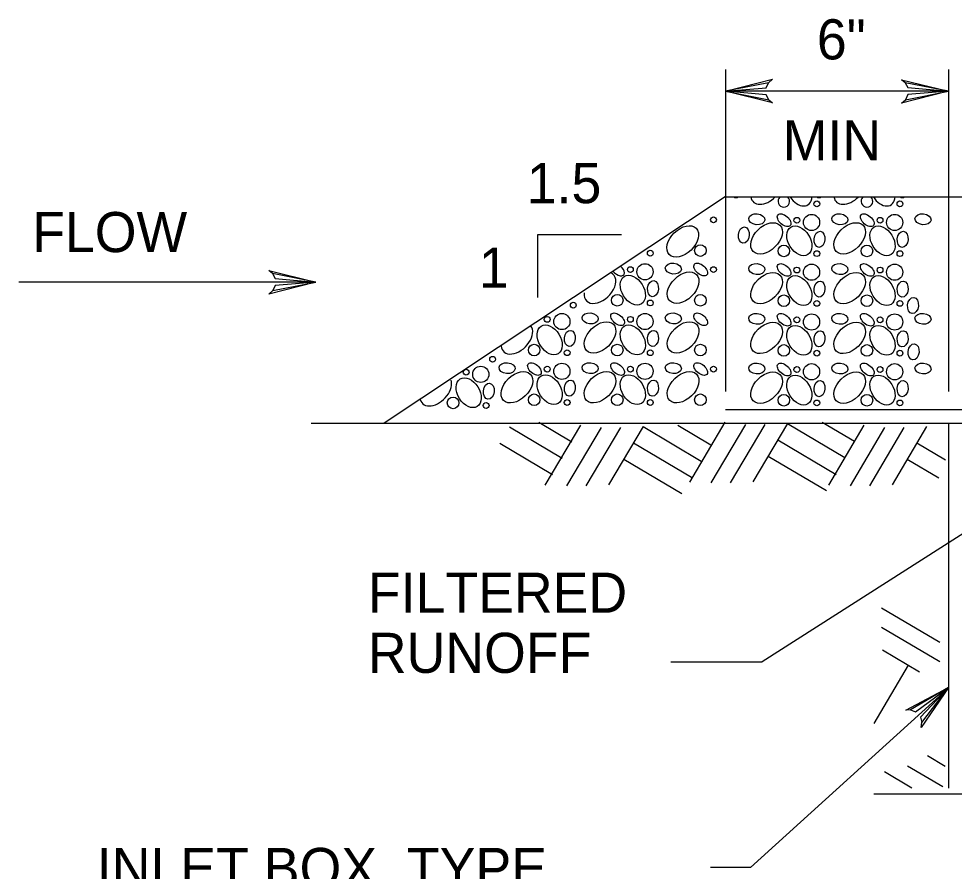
# Model space of a CAD drawing. Extents: x 636183 to 639890, y 299162 to 300538.
# Drawn here: x 637367.4 to 637437.3, y 299792.8 to 299856.5 of the extents above; entities that cross this region are included whole.
import ezdxf

# ---------------------------------------------------------------- set-up
doc = ezdxf.new("R2010")
doc.units = 0
doc.layers.add('Default', color=7, linetype='Continuous')

msp = doc.modelspace()

# ---------------------------------------------------------------- linework, layer by layer
at = {"layer": 'Default'}
for p, q in [((637436.88, 299852.669), (637436.88, 299828.614)), ((637420.211, 299843.151), (637394.729, 299826.243)), ((637420.211, 299843.151), (637445.22, 299843.151)), ((637406.216, 299835.651), (637406.216, 299840.337)), ((637406.216, 299840.337), (637412.465, 299840.337)), ((637420.235, 299827.262), (637489.98, 299827.262)), ((637406.277, 299826.319), (637408.745, 299824.856)), ((637420.181, 299826.319), (637417.528, 299821.842)), ((637427.459, 299826.319), (637429.864, 299824.894)), ((637389.258, 299826.243), (637420.235, 299826.243)), ((637404.076, 299825.979), (637408.025, 299823.639)), ((637409.394, 299826.096), (637406.741, 299821.62)), ((637410.929, 299825.914), (637408.352, 299821.565)), ((637412.379, 299825.914), (637409.802, 299821.565)), ((637414.07, 299825.994), (637411.493, 299821.645)), ((637414.07, 299825.994), (637418.42, 299823.417)), ((637416.672, 299826.096), (637419.14, 299824.633)), ((637421.717, 299826.136), (637419.139, 299821.787)), ((637420.235, 299826.243), (637489.98, 299826.243)), ((637423.166, 299826.136), (637420.589, 299821.787)), ((637424.858, 299826.217), (637422.28, 299821.868)), ((637424.858, 299826.217), (637429.143, 299823.678)), ((637430.576, 299826.096), (637427.923, 299821.62)), ((637432.111, 299825.914), (637429.534, 299821.565)), ((637433.561, 299825.914), (637430.984, 299821.565)), ((637435.252, 299825.994), (637432.675, 299821.645)), ((637436.88, 299826.243), (637436.88, 299798.98)), ((637424.137, 299825.001), (637428.486, 299822.423)), ((637403.355, 299824.763), (637407.304, 299822.423)), ((637413.349, 299824.778), (637417.699, 299822.201)), ((637448.335, 299824.623), (637422.968, 299808.402)), ((637434.532, 299824.778), (637436.675, 299823.508)), ((637412.629, 299823.562), (637416.978, 299820.985)), ((637423.416, 299823.785), (637427.765, 299821.207)), ((637433.811, 299823.562), (637436.178, 299822.159)), ((637436.234, 299809.849), (637431.885, 299812.426)), ((637436.234, 299808.399), (637431.885, 299810.977)), ((637434.73, 299807.647), (637431.966, 299809.285)), ((637416.154, 299808.402), (637422.968, 299808.402)), ((637433.882, 299808.15), (637431.305, 299803.8)), ((637436.766, 299806.354), (637422.107, 299793.047)), ((637436.639, 299800.597), (637435.318, 299801.38)), ((637436.457, 299799.062), (637433.823, 299800.622)), ((637434.149, 299798.98), (637432.108, 299800.19)), ((637431.312, 299798.538), (637455.154, 299798.538)), ((637422.107, 299793.047), (637419.109, 299793.047))]:
    msp.add_line(p, q, dxfattribs=at)
for points in [[(637420.235, 299852.669), (637420.235, 299828.614)], [(637423.467, 299850.419), (637423.736, 299850.196), (637420.235, 299851.057), (637423.467, 299850.419), (637423.271, 299850.792), (637420.235, 299851.057), (637423.264, 299851.316), (637423.447, 299851.691), (637420.235, 299851.057), (637423.729, 299851.945), (637423.447, 299851.691)], [(637433.648, 299851.694), (637433.379, 299851.918), (637436.88, 299851.057), (637433.648, 299851.694), (637433.845, 299851.321), (637436.88, 299851.057), (637433.851, 299850.798), (637433.669, 299850.422), (637436.88, 299851.057), (637433.386, 299850.169), (637433.669, 299850.422)], [(637436.88, 299851.057), (637420.235, 299851.057)], [(637386.377, 299837.422), (637386.107, 299837.645), (637389.609, 299836.784), (637386.377, 299837.422), (637386.573, 299837.049), (637389.609, 299836.784), (637386.579, 299836.525), (637386.397, 299836.15), (637389.609, 299836.784), (637386.114, 299835.896), (637386.397, 299836.15)], [(637389.609, 299836.784), (637367.415, 299836.784)], [(637434.042, 299804.815), (637433.693, 299804.803), (637436.881, 299806.487), (637434.042, 299804.815), (637434.437, 299804.667), (637436.881, 299806.487), (637434.79, 299804.28), (637434.903, 299803.878), (637436.881, 299806.487), (637434.86, 299803.501), (637434.903, 299803.878)]]:
    msp.add_lwpolyline(points, dxfattribs=at)
for centre, radius in [((637427.055, 299842.636), 0.217), ((637433.266, 299842.636), 0.217), ((637419.33, 299841.443), 0.217), ((637426.659, 299841.247), 0.606), ((637432.869, 299841.247), 0.606), ((637425.564, 299841.411), 0.217), ((637431.775, 299841.411), 0.217), ((637418.353, 299839.15), 0.435), ((637424.587, 299839.117), 0.435), ((637430.798, 299839.117), 0.435), ((637414.611, 299838.949), 0.217), ((637427.055, 299838.917), 0.217), ((637433.266, 299838.917), 0.217), ((637414.214, 299837.561), 0.606), ((637413.119, 299837.724), 0.217), ((637419.33, 299837.724), 0.217), ((637425.564, 299837.692), 0.217), ((637426.659, 299837.529), 0.606), ((637431.775, 299837.692), 0.217), ((637432.869, 299837.529), 0.606), ((637412.142, 299835.431), 0.435), ((637414.611, 299835.23), 0.217), ((637418.353, 299835.431), 0.435), ((637424.587, 299835.398), 0.435), ((637427.055, 299835.198), 0.217), ((637430.798, 299835.398), 0.435), ((637433.266, 299835.198), 0.217), ((637408.855, 299835.068), 0.217), ((637406.908, 299834.005), 0.217), ((637408.003, 299833.842), 0.606), ((637413.119, 299834.005), 0.217), ((637414.214, 299833.842), 0.606), ((637425.564, 299833.973), 0.217), ((637426.659, 299833.81), 0.606), ((637431.775, 299833.973), 0.217), ((637432.869, 299833.81), 0.606), ((637405.931, 299831.712), 0.435), ((637412.142, 299831.712), 0.435), ((637418.353, 299831.712), 0.435), ((637424.587, 299831.679), 0.435), ((637430.798, 299831.679), 0.435), ((637402.828, 299831.023), 0.217), ((637408.4, 299831.512), 0.217), ((637414.611, 299831.512), 0.217), ((637427.055, 299831.479), 0.217), ((637433.266, 299831.479), 0.217), ((637401.943, 299829.896), 0.606), ((637406.908, 299830.287), 0.217), ((637408.003, 299830.124), 0.606), ((637413.119, 299830.287), 0.217), ((637414.214, 299830.124), 0.606), ((637419.33, 299830.287), 0.217), ((637425.564, 299830.254), 0.217), ((637426.659, 299830.091), 0.606), ((637431.775, 299830.254), 0.217), ((637432.869, 299830.091), 0.606), ((637400.849, 299830.059), 0.217), ((637405.931, 299827.993), 0.435), ((637412.142, 299827.993), 0.435), ((637418.353, 299827.993), 0.435), ((637424.587, 299827.961), 0.435), ((637430.798, 299827.961), 0.435), ((637399.872, 299827.765), 0.435), ((637402.34, 299827.565), 0.217), ((637408.4, 299827.793), 0.217), ((637414.611, 299827.793), 0.217), ((637427.055, 299827.76), 0.217), ((637433.266, 299827.76), 0.217)]:
    msp.add_circle(centre, radius, dxfattribs=at)
for centre in [(637424.587, 299842.836), (637430.798, 299842.836)]:
    msp.add_arc(centre, 0.435, 133.46882, 46.53118, dxfattribs=at)
for centre, major_axis, ratio, start_param, end_param in [((637421.045, 299843.705), (0.061, 0.603), 0.672414, 2.796883, 3.62207), ((637423.296, 299843.776), (1.003, 0.982), 0.641702, 2.711952, 4.731495), ((637425.749, 299843.594), (-0.638, 1.03), 0.672414, 1.584156, 3.909428), ((637427.256, 299843.705), (0.061, 0.603), 0.672414, 2.796883, 3.62207), ((637429.507, 299843.776), (1.003, 0.982), 0.641702, 2.711952, 4.731495), ((637431.96, 299843.594), (-0.638, 1.03), 0.672414, 1.584156, 3.909428), ((637433.467, 299843.705), (0.061, 0.603), 0.672414, 2.796883, 3.62207), ((637410.851, 299836.371), (1.003, 0.982), 0.641702, 2.49155, 6.51241), ((637412.167, 299837.728), (0.459, -0.397), 0.56568, 4.409527, 7.849714), ((637404.64, 299832.587), (1.003, 0.982), 0.641702, 2.639106, 6.210766), ((637398.581, 299828.705), (1.003, 0.982), 0.641702, 2.787033, 6.002199)]:
    msp.add_ellipse(centre, major_axis=major_axis, ratio=ratio, start_param=start_param, end_param=end_param, dxfattribs=at)
for centre, major_axis, ratio in [((637422.564, 299841.486), (0.603, -0.061), 0.672414), ((637424.612, 299841.415), (0.459, -0.397), 0.56568), ((637428.775, 299841.486), (0.603, -0.061), 0.672414), ((637430.823, 299841.415), (0.459, -0.397), 0.56568), ((637434.986, 299841.486), (0.603, -0.061), 0.672414), ((637417.03, 299839.829), (1.003, 0.982), 0.641702), ((637423.296, 299840.057), (1.003, 0.982), 0.641702), ((637425.749, 299839.875), (-0.638, 1.03), 0.672414), ((637429.507, 299840.057), (1.003, 0.982), 0.641702), ((637431.96, 299839.875), (-0.638, 1.03), 0.672414), ((637421.597, 299840.305), (0.061, 0.603), 0.672414), ((637427.256, 299839.986), (0.061, 0.603), 0.672414), ((637433.467, 299839.986), (0.061, 0.603), 0.672414), ((637416.33, 299837.799), (0.603, -0.061), 0.672414), ((637418.378, 299837.728), (0.459, -0.397), 0.56568), ((637422.564, 299837.767), (0.603, -0.061), 0.672414), ((637424.612, 299837.696), (0.459, -0.397), 0.56568), ((637428.775, 299837.767), (0.603, -0.061), 0.672414), ((637430.823, 299837.696), (0.459, -0.397), 0.56568), ((637413.304, 299836.189), (-0.638, 1.03), 0.672414), ((637417.062, 299836.371), (1.003, 0.982), 0.641702), ((637423.296, 299836.338), (1.003, 0.982), 0.641702), ((637429.507, 299836.338), (1.003, 0.982), 0.641702), ((637414.811, 299836.3), (0.061, 0.603), 0.672414), ((637425.749, 299836.156), (-0.638, 1.03), 0.672414), ((637427.256, 299836.267), (0.061, 0.603), 0.672414), ((637431.96, 299836.156), (-0.638, 1.03), 0.672414), ((637433.467, 299836.267), (0.061, 0.603), 0.672414), ((637434.239, 299835.04), (0.061, 0.603), 0.672414), ((637410.119, 299834.08), (0.603, -0.061), 0.672414), ((637410.851, 299832.652), (1.003, 0.982), 0.641702), ((637412.167, 299834.009), (0.459, -0.397), 0.56568), ((637416.33, 299834.08), (0.603, -0.061), 0.672414), ((637417.062, 299832.652), (1.003, 0.982), 0.641702), ((637418.378, 299834.009), (0.459, -0.397), 0.56568), ((637422.564, 299834.048), (0.603, -0.061), 0.672414), ((637423.296, 299832.619), (1.003, 0.982), 0.641702), ((637424.612, 299833.977), (0.459, -0.397), 0.56568), ((637428.775, 299834.048), (0.603, -0.061), 0.672414), ((637429.507, 299832.619), (1.003, 0.982), 0.641702), ((637430.823, 299833.977), (0.459, -0.397), 0.56568), ((637434.986, 299834.048), (0.603, -0.061), 0.672414), ((637407.093, 299832.47), (-0.638, 1.03), 0.672414), ((637413.304, 299832.47), (-0.638, 1.03), 0.672414), ((637425.749, 299832.438), (-0.638, 1.03), 0.672414), ((637431.96, 299832.438), (-0.638, 1.03), 0.672414), ((637408.6, 299832.581), (0.061, 0.603), 0.672414), ((637414.811, 299832.581), (0.061, 0.603), 0.672414), ((637427.256, 299832.548), (0.061, 0.603), 0.672414), ((637433.467, 299832.548), (0.061, 0.603), 0.672414), ((637434.288, 299831.571), (0.061, 0.603), 0.672414), ((637403.908, 299830.362), (0.603, -0.061), 0.672414), ((637405.956, 299830.291), (0.459, -0.397), 0.56568), ((637410.119, 299830.362), (0.603, -0.061), 0.672414), ((637412.167, 299830.291), (0.459, -0.397), 0.56568), ((637416.33, 299830.362), (0.603, -0.061), 0.672414), ((637418.378, 299830.291), (0.459, -0.397), 0.56568), ((637422.564, 299830.329), (0.603, -0.061), 0.672414), ((637424.612, 299830.258), (0.459, -0.397), 0.56568), ((637428.775, 299830.329), (0.603, -0.061), 0.672414), ((637430.823, 299830.258), (0.459, -0.397), 0.56568), ((637434.986, 299830.329), (0.603, -0.061), 0.672414), ((637401.034, 299828.524), (-0.638, 1.03), 0.672414), ((637404.64, 299828.933), (1.003, 0.982), 0.641702), ((637407.093, 299828.751), (-0.638, 1.03), 0.672414), ((637410.851, 299828.933), (1.003, 0.982), 0.641702), ((637413.304, 299828.751), (-0.638, 1.03), 0.672414), ((637417.062, 299828.933), (1.003, 0.982), 0.641702), ((637423.296, 299828.901), (1.003, 0.982), 0.641702), ((637425.749, 299828.719), (-0.638, 1.03), 0.672414), ((637429.507, 299828.901), (1.003, 0.982), 0.641702), ((637431.96, 299828.719), (-0.638, 1.03), 0.672414), ((637402.541, 299828.634), (0.061, 0.603), 0.672414), ((637408.6, 299828.862), (0.061, 0.603), 0.672414), ((637414.811, 299828.862), (0.061, 0.603), 0.672414), ((637427.256, 299828.829), (0.061, 0.603), 0.672414), ((637433.467, 299828.829), (0.061, 0.603), 0.672414)]:
    msp.add_ellipse(centre, major_axis=major_axis, ratio=ratio, dxfattribs=at)

# ---------------------------------------------------------------- texts
for s, height, p in [('6"', 2.998, (637427.056, 299853.431)), ('MIN', 2.998, (637424.506, 299845.883)), ('1.5', 2.998, (637405.376, 299842.686)), ('FLOW', 2.998, (637368.421, 299839.029)), ('1', 2.998, (637401.796, 299836.372)), ('FILTERED', 2.998, (637393.502, 299812.081)), ('RUNOFF', 2.998, (637393.502, 299807.584)), ('INLET BOX, TYPE', 2.99804, (637373.25, 299791.507))]:
    msp.add_text(s, height=height, dxfattribs=at).set_placement(p)

doc.saveas('drawing.dxf')
